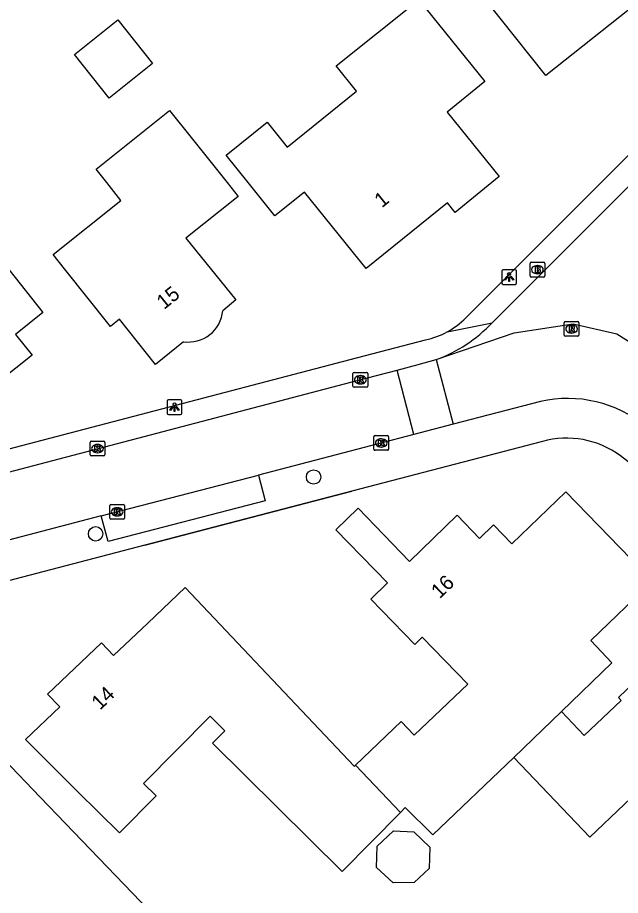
# Model space of a CAD drawing. Extents: x 159503 to 160347, y 382525 to 383272.
# Drawn here: x 159893.2 to 159934.2, y 382951.5 to 383011.2 of the extents above; entities that cross this region are included whole.
import ezdxf

# ---------------------------------------------------------------- set-up
doc = ezdxf.new("R2010")
doc.units = 0
for name, color, linetype in [('IMGEO_Boom', 7, 'Continuous'), ('IMGEO_Brandkraan', 7, 'Continuous'), ('IMGEO_Kolk', 7, 'Continuous'), ('IMGEO_Lichtpunt', 7, 'Continuous'), ('IMGEO_Muur', 7, 'Continuous'), ('IMGEO_Pand', 7, 'Continuous'), ('IMGEO_Pand_nummerreeks', 7, 'Continuous'), ('IMGEO_Rijbaan_lokaal_open', 7, 'Continuous'), ('IMGEO_Rioolput', 7, 'Continuous')]:
    doc.layers.add(name, color=color, linetype=linetype)

msp = doc.modelspace()

# ---------------------------------------------------------------- linework, layer by layer
at = {"layer": 'IMGEO_Boom'}
for centre in [(159913.368, 382979.983), (159898.537, 382976.121)]:
    msp.add_circle(centre, 0.489, dxfattribs=at)
at = {"layer": 'IMGEO_Brandkraan'}
for p, q in [((159928.094, 382993.656), (159928.094, 382994.508)), ((159928.169, 382994.582), (159929.021, 382994.582)), ((159928.582, 382994.362), (159928.607, 382994.362)), ((159929.095, 382994.508), (159929.095, 382993.656)), ((159929.021, 382993.582), (159928.169, 382993.582)), ((159928.605, 382993.802), (159928.58, 382993.802))]:
    msp.add_line(p, q, dxfattribs=at)
for points in [[(159928.094, 382993.656), (159928.094, 382994.508)], [(159928.169, 382994.582), (159929.021, 382994.582)], [(159928.442, 382994.282), (159928.442, 382993.882), (159928.655, 382993.882)], [(159928.673, 382994.282), (159928.442, 382994.282)], [(159928.621, 382994.201), (159928.567, 382994.201), (159928.567, 382994.125)], [(159928.567, 382994.125), (159928.62, 382994.125)], [(159928.629, 382994.049), (159928.567, 382994.049), (159928.567, 382993.968)], [(159929.095, 382994.508), (159929.095, 382993.656)], [(159929.021, 382993.582), (159928.169, 382993.582)], [(159928.567, 382993.968), (159928.629, 382993.968)]]:
    msp.add_lwpolyline(points, dxfattribs=at)
for centre, radius, start, end in [((159928.171, 382994.506), 0.0765, 91.55205, 178.44795), ((159928.171, 382994.506), 0.0765, 91.55205, 178.44795), ((159928.622, 382994.163), 0.0379, 267.82845, 90.93552), ((159928.63, 382994.008), 0.0404, 269.87594, 90.50774), ((159928.677, 382994.137), 0.145, 59.4692, 91.53667), ((159928.702, 382994.184), 0.0922, 285.51372, 58.15012), ((159928.707, 382993.992), 0.105, 301.31148, 78.98903), ((159929.019, 382994.506), 0.0765, 1.55205, 88.44795), ((159929.019, 382994.506), 0.0765, 1.55205, 88.44795), ((159928.171, 382993.658), 0.0765, 181.55205, 268.44795), ((159928.171, 382993.658), 0.0765, 181.55205, 268.44795), ((159928.661, 382994.133), 0.251, 268.66757, 293.53466), ((159929.019, 382993.658), 0.0765, 271.55205, 358.44795), ((159929.019, 382993.658), 0.0765, 271.55205, 358.44795)]:
    msp.add_arc(centre, radius, start, end, dxfattribs=at)
for centre, major_axis, ratio, start_param, end_param in [((159928.581, 382994.082), (-0.387, 0.002), 0.722429, 4.712389, 7.853982), ((159928.606, 382994.082), (-0.39, 0.002), 0.717154, 1.570796, 4.712389)]:
    msp.add_ellipse(centre, major_axis=major_axis, ratio=ratio, start_param=start_param, end_param=end_param, dxfattribs=at)
at = {"layer": 'IMGEO_Kolk'}
for p, q in [((159916.047, 382986.17), (159916.047, 382987.022)), ((159916.122, 382987.096), (159916.974, 382987.096)), ((159916.535, 382986.876), (159916.56, 382986.876)), ((159917.048, 382987.022), (159917.048, 382986.17)), ((159916.558, 382986.316), (159916.533, 382986.316)), ((159916.974, 382986.096), (159916.122, 382986.096)), ((159917.472, 382981.872), (159917.472, 382982.724)), ((159917.547, 382982.798), (159918.399, 382982.798)), ((159918.473, 382982.724), (159918.473, 382981.872)), ((159898.167, 382981.488), (159898.167, 382982.34)), ((159898.242, 382982.414), (159899.094, 382982.414)), ((159898.655, 382982.194), (159898.68, 382982.194)), ((159899.168, 382982.34), (159899.168, 382981.488)), ((159917.96, 382982.578), (159917.985, 382982.578)), ((159898.678, 382981.634), (159898.653, 382981.634)), ((159918.399, 382981.798), (159917.547, 382981.798)), ((159917.983, 382982.018), (159917.958, 382982.018)), ((159899.094, 382981.414), (159898.242, 382981.414)), ((159899.503, 382977.187), (159899.503, 382978.039)), ((159899.578, 382978.113), (159900.43, 382978.113)), ((159900.504, 382978.039), (159900.504, 382977.187)), ((159900.014, 382977.333), (159899.989, 382977.333)), ((159899.991, 382977.893), (159900.016, 382977.893)), ((159900.43, 382977.113), (159899.578, 382977.113))]:
    msp.add_line(p, q, dxfattribs=at)
for points in [[(159916.047, 382986.17), (159916.047, 382987.022)], [(159916.122, 382987.096), (159916.974, 382987.096)], [(159917.048, 382987.022), (159917.048, 382986.17)], [(159916.368, 382986.796), (159916.491, 382986.796), (159916.491, 382986.645), (159916.621, 382986.796), (159916.785, 382986.796), (159916.639, 382986.645), (159916.792, 382986.396), (159916.64, 382986.396), (159916.555, 382986.56), (159916.491, 382986.493), (159916.491, 382986.396), (159916.368, 382986.396), (159916.368, 382986.796)], [(159916.974, 382986.096), (159916.122, 382986.096)], [(159917.472, 382981.872), (159917.472, 382982.724)], [(159917.547, 382982.798), (159918.399, 382982.798)], [(159918.473, 382982.724), (159918.473, 382981.872)], [(159898.167, 382981.488), (159898.167, 382982.34)], [(159898.242, 382982.414), (159899.094, 382982.414)], [(159898.488, 382982.114), (159898.611, 382982.114), (159898.611, 382981.963), (159898.741, 382982.114), (159898.905, 382982.114), (159898.759, 382981.963), (159898.912, 382981.714), (159898.76, 382981.714), (159898.675, 382981.878), (159898.611, 382981.811), (159898.611, 382981.714), (159898.488, 382981.714), (159898.488, 382982.114)], [(159899.168, 382982.34), (159899.168, 382981.488)], [(159917.793, 382982.498), (159917.916, 382982.498), (159917.916, 382982.347), (159918.046, 382982.498), (159918.21, 382982.498), (159918.064, 382982.347), (159918.217, 382982.098), (159918.065, 382982.098), (159917.98, 382982.262), (159917.916, 382982.195), (159917.916, 382982.098), (159917.793, 382982.098), (159917.793, 382982.498)], [(159918.399, 382981.798), (159917.547, 382981.798)], [(159899.094, 382981.414), (159898.242, 382981.414)], [(159899.503, 382977.187), (159899.503, 382978.039)], [(159899.578, 382978.113), (159900.43, 382978.113)], [(159900.504, 382978.039), (159900.504, 382977.187)], [(159899.824, 382977.813), (159899.947, 382977.813), (159899.947, 382977.662), (159900.077, 382977.813), (159900.241, 382977.813), (159900.095, 382977.662), (159900.248, 382977.413), (159900.096, 382977.413), (159900.011, 382977.577), (159899.947, 382977.51), (159899.947, 382977.413), (159899.824, 382977.413), (159899.824, 382977.813)], [(159900.43, 382977.113), (159899.578, 382977.113)]]:
    msp.add_lwpolyline(points, dxfattribs=at)
for centre, start, end in [((159916.124, 382987.02), 91.55205, 178.44795), ((159916.124, 382987.02), 91.55205, 178.44795), ((159916.972, 382987.02), 1.55205, 88.44795), ((159916.972, 382987.02), 1.55205, 88.44795), ((159916.124, 382986.172), 181.55205, 268.44795), ((159916.124, 382986.172), 181.55205, 268.44795), ((159916.972, 382986.172), 271.55205, 358.44795), ((159916.972, 382986.172), 271.55205, 358.44795), ((159917.549, 382982.722), 91.55205, 178.44795), ((159917.549, 382982.722), 91.55205, 178.44795), ((159918.397, 382982.722), 1.55205, 88.44795), ((159918.397, 382982.722), 1.55205, 88.44795), ((159898.244, 382982.338), 91.55205, 178.44795), ((159898.244, 382982.338), 91.55205, 178.44795), ((159899.092, 382982.338), 1.55205, 88.44795), ((159899.092, 382982.338), 1.55205, 88.44795), ((159917.549, 382981.874), 181.55205, 268.44795), ((159917.549, 382981.874), 181.55205, 268.44795), ((159918.397, 382981.874), 271.55205, 358.44795), ((159918.397, 382981.874), 271.55205, 358.44795), ((159898.244, 382981.49), 181.55205, 268.44795), ((159898.244, 382981.49), 181.55205, 268.44795), ((159899.092, 382981.49), 271.55205, 358.44795), ((159899.092, 382981.49), 271.55205, 358.44795), ((159899.58, 382978.037), 91.55205, 178.44795), ((159899.58, 382978.037), 91.55205, 178.44795), ((159900.428, 382978.037), 1.55205, 88.44795), ((159900.428, 382978.037), 1.55205, 88.44795), ((159899.58, 382977.189), 181.55205, 268.44795), ((159899.58, 382977.189), 181.55205, 268.44795), ((159900.428, 382977.189), 271.55205, 358.44795), ((159900.428, 382977.189), 271.55205, 358.44795)]:
    msp.add_arc(centre, 0.0765, start, end, dxfattribs=at)
for centre, major_axis, ratio, start_param, end_param in [((159916.534, 382986.596), (-0.387, 0.002), 0.722429, 4.712389, 7.853982), ((159916.559, 382986.596), (-0.39, 0.002), 0.717154, 1.570796, 4.712389), ((159898.654, 382981.914), (-0.387, 0.002), 0.722429, 4.712389, 7.853982), ((159898.679, 382981.914), (-0.39, 0.002), 0.717154, 1.570796, 4.712389), ((159917.959, 382982.298), (-0.387, 0.002), 0.722429, 4.712389, 7.853982), ((159917.984, 382982.298), (-0.39, 0.002), 0.717154, 1.570796, 4.712389), ((159899.99, 382977.613), (-0.387, 0.002), 0.722429, 4.712389, 7.853982), ((159900.015, 382977.613), (-0.39, 0.002), 0.717154, 1.570796, 4.712389)]:
    msp.add_ellipse(centre, major_axis=major_axis, ratio=ratio, start_param=start_param, end_param=end_param, dxfattribs=at)
at = {"layer": 'IMGEO_Lichtpunt'}
for p, q in [((159927.071, 382994.079), (159926.263, 382994.079)), ((159927.071, 382994.079), (159926.263, 382994.079)), ((159926.169, 382993.984), (159926.169, 382993.177)), ((159926.169, 382993.984), (159926.169, 382993.177)), ((159927.165, 382993.177), (159927.165, 382993.984)), ((159927.165, 382993.177), (159927.165, 382993.984)), ((159926.263, 382993.083), (159927.071, 382993.083)), ((159926.263, 382993.083), (159927.071, 382993.083)), ((159903.404, 382985.135), (159903.404, 382984.328)), ((159903.404, 382985.135), (159903.404, 382984.328)), ((159904.306, 382985.23), (159903.498, 382985.23)), ((159904.306, 382985.23), (159903.498, 382985.23)), ((159904.4, 382984.328), (159904.4, 382985.135)), ((159904.4, 382984.328), (159904.4, 382985.135)), ((159903.498, 382984.234), (159904.306, 382984.234)), ((159903.498, 382984.234), (159904.306, 382984.234))]:
    msp.add_line(p, q, dxfattribs=at)
for points in [[(159926.543, 382993.648), (159926.582, 382993.62), (159926.394, 382993.358), (159926.356, 382993.385), (159926.543, 382993.648)], [(159926.645, 382993.6), (159926.692, 382993.6), (159926.692, 382993.278), (159926.645, 382993.278), (159926.645, 382993.6)], [(159926.755, 382993.62), (159926.793, 382993.647), (159926.98, 382993.385), (159926.941, 382993.357), (159926.755, 382993.62)], [(159903.778, 382984.799), (159903.817, 382984.771), (159903.629, 382984.509), (159903.591, 382984.536), (159903.778, 382984.799)], [(159903.88, 382984.751), (159903.927, 382984.751), (159903.927, 382984.429), (159903.88, 382984.429), (159903.88, 382984.751)], [(159903.99, 382984.771), (159904.028, 382984.798), (159904.215, 382984.536), (159904.176, 382984.508), (159903.99, 382984.771)]]:
    msp.add_lwpolyline(points, dxfattribs=at)
for centre in [(159926.668, 382993.782), (159903.903, 382984.933)]:
    msp.add_circle(centre, 0.0994, dxfattribs=at)
for centre, start, end in [((159926.263, 382993.984), 90, 180), ((159926.263, 382993.984), 90, 180), ((159927.071, 382993.984), 0, 90), ((159927.071, 382993.984), 0, 90), ((159926.263, 382993.177), 180, 270), ((159926.263, 382993.177), 180, 270), ((159927.071, 382993.177), 270, 0), ((159927.071, 382993.177), 270, 360), ((159903.498, 382985.135), 90, 180), ((159903.498, 382985.135), 90, 180), ((159904.306, 382985.135), 0, 90), ((159904.306, 382985.135), 0, 90), ((159903.498, 382984.328), 180, 270), ((159903.498, 382984.328), 180, 270), ((159904.306, 382984.328), 270, 0), ((159904.306, 382984.328), 270, 360)]:
    msp.add_arc(centre, 0.0946, start, end, dxfattribs=at)
at = {"layer": 'IMGEO_Muur'}
msp.add_lwpolyline([(159901.888, 382975.342), (159915.972, 382979.015)], dxfattribs=at)
at = {"layer": 'IMGEO_Pand'}
for points in [[(159934.607, 383023.679), (159937.389, 383020.178), (159940.5, 383016.264), (159939.742, 383015.645), (159940.661, 383014.477), (159936.296, 383011.004), (159935.312, 383012.158), (159934.206, 383011.278), (159929.175, 383007.274), (159926.065, 383011.19), (159923.902, 383013.912), (159927.587, 383016.839), (159926.974, 383017.613), (159934.607, 383023.679)], [(159925.022, 383006.875), (159922.445, 383004.799), (159925.983, 383000.407), (159925.485, 383000), (159922.998, 382997.968), (159922.486, 382998.616), (159916.947, 382994.156), (159912.758, 382999.359), (159910.741, 382997.735), (159908.917, 383000), (159907.417, 383001.863), (159910.206, 383004.109), (159911.576, 383002.409), (159916.297, 383006.211), (159914.908, 383007.936), (159920.524, 383012.459), (159925.022, 383006.875)], [(159902.416, 383008.097), (159899.467, 383005.742), (159897.093, 383008.716), (159900.042, 383011.071), (159902.416, 383008.097)], [(159904.515, 382989.184), (159902.617, 382987.628), (159900.164, 382990.716), (159899.546, 382990.223), (159896.432, 382994.135), (159895.651, 382995.117), (159900.256, 382998.794), (159899.293, 383000), (159898.568, 383000.909), (159903.571, 383004.903), (159905.124, 383002.958)], [(159894.942, 382991.159), (159893.091, 382989.678), (159894.215, 382988.264), (159888.873, 382984.022), (159888.321, 382984.712), (159885.369, 382982.351), (159882.993, 382985.322), (159885.518, 382987.338), (159883.921, 382989.337), (159884.351, 382989.68), (159884.221, 382989.845), (159886.312, 382991.518), (159885.968, 382991.947), (159886.32, 382992.228), (159884.772, 382994.165), (159880.641, 382999.333), (159885.405, 383003.14), (159889.353, 382998.199), (159891.833, 382995.075), (159894.942, 382991.159)], [(159905.124, 383002.958), (159907.486, 383000), (159908.244, 382999.05), (159904.681, 382996.226), (159908.084, 382992.039), (159907.187, 382991.287)], [(159916.211, 382960.394), (159919.327, 382963.349), (159920.208, 382962.421), (159923.869, 382965.893), (159920.764, 382969.094), (159920.247, 382968.592), (159917.253, 382971.679), (159918.389, 382972.78), (159914.883, 382976.395), (159916.389, 382977.855), (159919.894, 382974.24), (159923.132, 382977.38), (159924.656, 382975.807), (159925.603, 382976.725), (159926.856, 382975.432), (159930.517, 382978.982), (159936.424, 382972.89), (159932.235, 382968.858), (159933.664, 382967.34), (159930.234, 382964.041)], [(159919.286, 382957.181), (159915.304, 382953.166), (159906.499, 382961.897), (159907.322, 382962.727), (159906.327, 382963.712), (159901.799, 382959.146), (159902.651, 382958.301), (159900.158, 382955.787), (159897.314, 382958.607), (159893.764, 382962.128), (159896.102, 382964.364), (159895.276, 382965.221), (159898.928, 382968.717), (159899.762, 382967.852), (159902.084, 382970.054), (159904.621, 382972.46), (159916.134, 382960.321), (159916.211, 382960.394)], [(159930.234, 382964.041), (159931.771, 382962.416), (159934.286, 382964.793), (159934.106, 382964.998), (159941.347, 382971.931), (159944.155, 382968.989), (159943.448, 382968.307), (159944.994, 382966.583), (159945.743, 382967.327), (159946.261, 382966.792), (159944.645, 382965.232), (159947.554, 382962.207), (159943.937, 382958.756), (159940.81, 382955.771), (159936.827, 382959.946), (159932.161, 382955.493), (159926.984, 382960.92)], [(159926.984, 382960.92), (159930.234, 382964.041)], [(159907.313, 382945.183), (159900.827, 382938.914), (159897.232, 382935.438), (159894.674, 382938.1), (159900.812, 382943.991), (159894.496, 382950.57), (159892.322, 382948.482), (159892.55, 382948.243), (159890.969, 382946.724), (159890.739, 382946.962), (159888.565, 382944.875), (159889.604, 382943.791), (159889.387, 382943.583), (159884.743, 382948.422), (159887.876, 382951.451), (159886.365, 382953.023), (159889.496, 382955.951), (159890.709, 382957.085), (159888.649, 382959.263), (159891.294, 382961.807), (159894.763, 382958.206), (159907.313, 382945.183)], [(159926.984, 382960.92), (159921.486, 382955.642), (159919.607, 382957.505), (159919.286, 382957.181)], [(159916.211, 382960.394), (159919.286, 382957.181)], [(159918.772, 382952.396), (159917.654, 382953.44), (159917.683, 382954.882), (159918.795, 382955.918), (159920.181, 382955.865), (159921.269, 382954.812), (159921.24, 382953.373), (159920.201, 382952.406), (159918.772, 382952.396)]]:
    msp.add_lwpolyline(points, dxfattribs=at)
msp.add_arc((159904.85, 382991.507), 2.347, 261.79798, 354.61111, dxfattribs=at)
at = {"layer": 'IMGEO_Rijbaan_lokaal_open'}
for points in [[(159923.721, 382990.801), (159932.922, 383000), (159934.742, 383001.82), (159994.392, 383061.861)], [(159995.495, 383061.001), (159935.774, 383000.752), (159935.074, 383000), (159925.512, 382990.469)], [(159922.46, 382989.858), (159925.512, 382990.469)], [(159921.709, 382987.969), (159927.002, 382989.777), (159931.031, 382990.397), (159934.007, 382989.715), (159936.514, 382988.127)], [(159886.41, 382980.261), (159915.857, 382987.966), (159920.985, 382989.308)], [(159919.044, 382987.249), (159920.492, 382987.628), (159921.709, 382987.969)], [(159921.709, 382987.969), (159922.855, 382983.571)], [(159889.904, 382979.618), (159916.332, 382986.539), (159919.044, 382987.249)], [(159920.184, 382982.875), (159919.044, 382987.249)], [(159928.804, 382985.122), (159922.855, 382983.571)], [(159922.855, 382983.571), (159920.184, 382982.875)], [(159920.184, 382982.875), (159917.762, 382982.244), (159909.612, 382980.119)], [(159928.942, 382982.398), (159915.972, 382979.015), (159901.888, 382975.342), (159891.539, 382972.643)], [(159967.231, 382955.939), (159938.787, 382977.935), (159934.243, 382981.423)], [(159909.612, 382980.119), (159910.074, 382978.363), (159899.395, 382975.593), (159898.927, 382977.333)], [(159898.927, 382977.333), (159909.612, 382980.119)], [(159898.927, 382977.333), (159891.196, 382975.318)]]:
    msp.add_lwpolyline(points, dxfattribs=at)
for centre, radius, start, end in [((159918.308, 382997.285), 9.917, 290.05514, 316.58476), ((159919.822, 382994.7), 5.514, 298.58025, 314.99944), ((159919.816, 382994.696), 5.513, 282.24192, 298.65718), ((159930.645, 382976.933), 8.394, 50.59081, 102.67174), ((159930.6, 382976.512), 6.115, 53.42901, 105.7274)]:
    msp.add_arc(centre, radius, start, end, dxfattribs=at)
at = {"layer": 'IMGEO_Rioolput'}
for p, q in [((159930.42, 382989.625), (159930.42, 382990.477)), ((159930.495, 382990.551), (159931.347, 382990.551)), ((159931.421, 382990.477), (159931.421, 382989.625)), ((159930.908, 382990.331), (159930.933, 382990.331)), ((159931.347, 382989.551), (159930.495, 382989.551)), ((159930.931, 382989.771), (159930.906, 382989.771))]:
    msp.add_line(p, q, dxfattribs=at)
for points in [[(159930.42, 382989.625), (159930.42, 382990.477)], [(159930.495, 382990.551), (159931.347, 382990.551)], [(159931.421, 382990.477), (159931.421, 382989.625)], [(159931.009, 382990.249), (159930.757, 382990.251), (159930.757, 382989.851)], [(159930.757, 382989.851), (159930.881, 382989.851), (159930.881, 382990.013), (159930.892, 382990.013)], [(159930.935, 382990.17), (159930.881, 382990.17), (159930.881, 382990.089)], [(159930.881, 382990.089), (159930.933, 382990.089)], [(159930.939, 382989.984), (159931.01, 382989.851), (159931.15, 382989.851), (159931.085, 382989.977)], [(159931.347, 382989.551), (159930.495, 382989.551)]]:
    msp.add_lwpolyline(points, dxfattribs=at)
for centre, radius, start, end in [((159930.497, 382990.475), 0.0765, 91.55205, 178.44795), ((159930.497, 382990.475), 0.0765, 91.55205, 178.44795), ((159931.345, 382990.475), 0.0765, 1.55205, 88.44795), ((159931.345, 382990.475), 0.0765, 1.55205, 88.44795), ((159930.891, 382989.96), 0.0533, 26.02933, 88.69889), ((159930.917, 382990.278), 0.19, 274.7715, 282.96867), ((159930.941, 382990.074), 0.0964, 77.00612, 93.18647), ((159930.955, 382990.131), 0.0378, 276.66336, 79.67722), ((159931.008, 382990.139), 0.109, 350.36119, 89.41601), ((159931.006, 382990.139), 0.112, 277.58423, 350.98172), ((159930.99, 382989.924), 0.108, 29.51342, 73.79051), ((159930.497, 382989.627), 0.0765, 181.55205, 268.44795), ((159930.497, 382989.627), 0.0765, 181.55205, 268.44795), ((159931.345, 382989.627), 0.0765, 271.55205, 358.44795), ((159931.345, 382989.627), 0.0765, 271.55205, 358.44795)]:
    msp.add_arc(centre, radius, start, end, dxfattribs=at)
for centre, major_axis, ratio, start_param, end_param in [((159930.907, 382990.051), (-0.387, 0.002), 0.722429, 4.712389, 7.853982), ((159930.932, 382990.051), (-0.39, 0.002), 0.717154, 1.570796, 4.712389)]:
    msp.add_ellipse(centre, major_axis=major_axis, ratio=ratio, start_param=start_param, end_param=end_param, dxfattribs=at)

# ---------------------------------------------------------------- texts
at = {"layer": 'IMGEO_Pand_nummerreeks'}
for s, rotation, p in [('1', 38.84081, (159918.011, 382998.249)), ('15', 38.89801, (159903.196, 382991.333)), ('16', 44.11775, (159921.948, 382971.663)), ('14', 43.74976, (159898.839, 382964.091))]:
    msp.add_text(s, height=1, rotation=rotation, dxfattribs=at).set_placement(p)

doc.saveas('drawing.dxf')
